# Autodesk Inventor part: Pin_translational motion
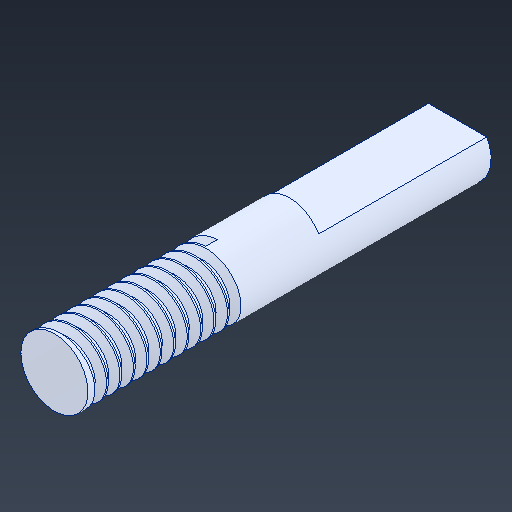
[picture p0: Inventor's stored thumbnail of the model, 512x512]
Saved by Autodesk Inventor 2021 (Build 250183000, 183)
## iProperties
Created: 2020-06
Part Number: Pin_translational motion
Material: SOLIDWORKS Materials|1060 Alloy
Document SubType Name: Modeling
Designer: ftrauzettel
Density: 2.7 g/cm^3
Appearance: 221,232,255
Author: ftrauzettel
Sending System: SolidWorks 2016
Last Author: Pam
Last Saved: 2020-06-01
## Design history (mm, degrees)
thread "Thread1"
body "Solid1"
